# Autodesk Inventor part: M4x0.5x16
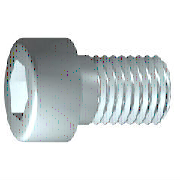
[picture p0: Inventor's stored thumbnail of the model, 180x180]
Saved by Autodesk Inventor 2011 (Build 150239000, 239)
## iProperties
Created: 2014-07
Part Number: M4x0.5x16
Material: 강, 연강
Description: 6각머리 태핑 나사
Document SubType Name: Modeling
Standard: KS B 1003
Designer: KYOUNG IL JANG
Standards Organization: KS
Language: ko-KR
Size Designation: M 4 x 16
Categories: <MemberInstance><Categories><Category DisplayName="조임쇠" InternalName="e4da775c-781d-43d5-af7c-5136215cf5a6" Mnemonic="FSTN"><Category DisplayName="볼트" InternalN
Density: 1 g/cm^3
Company: 한국ATC센터
IsCustomPart: 1
Author: KYOUNG IL JANG
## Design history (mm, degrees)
workplane "Work Plane1"
fillet "Fillet2" dims "d30" = 0.1 (= R)
revolve "본체" stored, may be unused: angle "d10" = 90 deg
sketch "스케치2"
  geometry: L1 (0, -4.9)-(0, 4.9) reference; L2 (-4.9, 0)-(4.9, 0) reference; L3 (1.732, 0)-(0.866, -1.5); L4 (0.866, -1.5)-(-0.866, -1.5); L5 (-0.866, -1.5)-(-1.732, 0); L6 (-1.732, 0)-(-0.866, 1.5); L7 (-0.866, 1.5)-(0.866, 1.5); L8 (0.866, 1.5)-(1.732, 0); 2 further points
  constraints: 12 end point, 1 coincident, 1 horizontal alignment, 1 point on line, 12 other
extrude "슬롯" join sketch "스케치2" stored distance "d11" = 10; taper "d12" = 0 deg
body "Solid1"
fillet "모깎기1" dims "d17" = 0.4 (= RR)
feature "스레드" dims "d13" = 14.25 (= GEL), "d14" = 0
chamfer "모따기1" distance "d15" = 0.42941 (= -0.5 x SPD + 0.5 x GD); stored, may be unused: second distance "d16" = 0.42941 (= GUL), angle "d27" = 45 deg
sketch "스케치1"
  geometry: L1 (-1, 0)-(16, 0); L2 (16, 0)-(16, 2); L3 (16, 2)-(1.75, 2); L4 (1.75, 2)-(1.32, 2); L5 (1.32, 2)-(0, 2); L6 (0, 2)-(0, 3.5); L7 (0, 3.5)-(-4, 3.5); L8 (-4, 3.5)-(-4, 1.732); L9 (-4, 1.732)-(-2, 1.732); L10 (-2, 1.732)-(-1, 0); L11 (-8, 0)-(20, 0) reference; L12 (0, -0.7)-(0, 4.2) reference; L13 (1.75, 2)-(0, 2)
  constraints: 22 end point, 6 parallel, 2 collinear, 2 perpendicular, 1 horizontal, 1 point on line
  dimensions: "d1" = 14.25 distance from line of L3.end L2 (= GEL); "d2" = 0.42952 distance of L4.end L3.end (computed from GAL); "d3" = 4 distance between parallel lines of L8 L6 (= KOH); "d4" = 2 distance of L8.end L9.end (= INTI); "d5" = 60 deg angle of L10 L1; "d6" = 4 diameter of L3 L1 (= GD); "d7" = 4 diameter of L5 L1 (= BDM); "d8" = 3.4641 diameter of L9 L1 (= 1.1547 x SW); "d9" = 7 diameter of L7 L1 (= KOD); "d26" = 16 distance between parallel lines of L12 L2 (= NLG)
other parameters: "GD" = 4 (= NND) [user parameter; used in 2 equation terms], "NLG" = 16 [user parameter; used in 1 equation term], "GEL" = 14.25 [user parameter; used in 2 equation terms], "KOD" = 7 [user parameter; used in 1 equation term], "KOH" = 4 [user parameter; used in 1 equation term], "INTI" = 2 [user parameter; used in 1 equation term], "GAL" = 0.42941 (= 0.61345 x PTC) [user parameter; used in 1 equation term], "GUL" = 0.42941 (= 0.61345 x PTC) [user parameter; used in 1 equation term], "BDM" = 4 (= NND) [user parameter; used in 1 equation term], "SW" = 3 [user parameter; used in 2 equation terms], "RR" = 0.4 [user parameter; used in 1 equation term], "SPD" = 3.14117 (= NND - 1.2269 x PTC) [user parameter; used in 1 equation term], "d19" = 0, "d28" = 0, "d29" = 0, "R" = 0.1 [user parameter; used in 1 equation term], "PHH" = 0.2 [user parameter], "GD1" = 3.14117 (= THREADDIA - 1.2269 x PTC) [user parameter], "THREADDIA" = 4 [user parameter; used in 1 equation term], "FAWI" = 45 deg [user parameter], "TPU" = 14.28571 (computed from PTC) [user parameter], "PTC" = 0.7 [user parameter; used in 5 equation terms], "NND" = 4 [user parameter; used in 3 equation terms], "TOA" = 30 deg [user parameter], "E0" = 3.465 (= 1.155 x SW) [user parameter]
